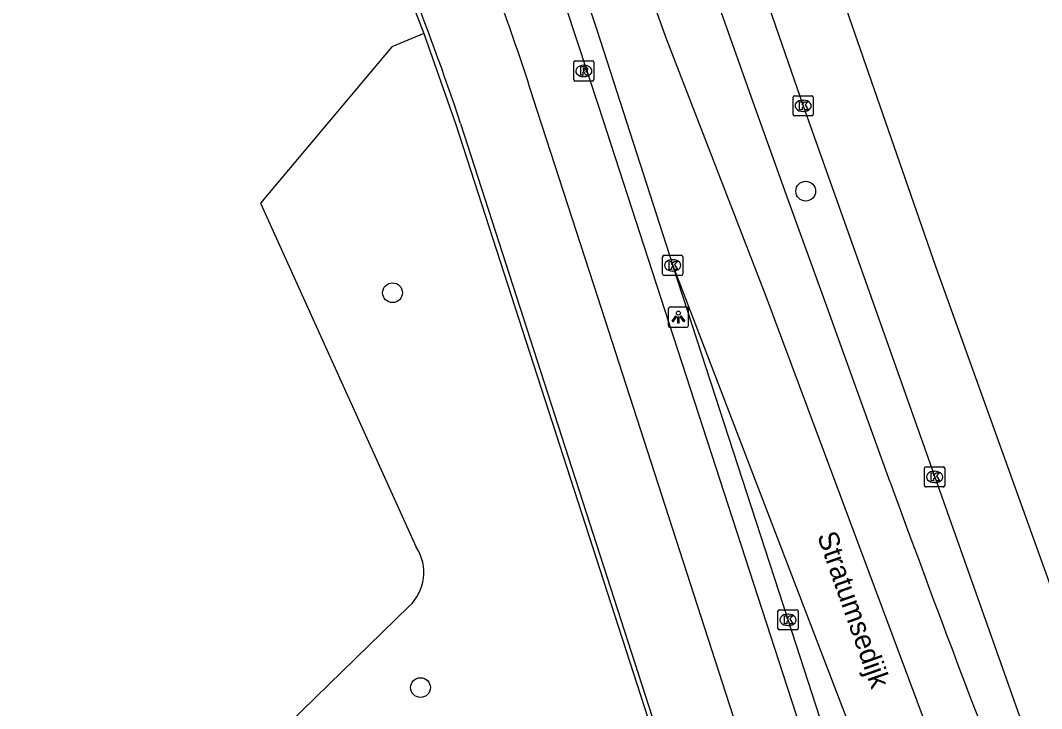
# Model space of a CAD drawing. Extents: x 161402 to 161933, y 381650 to 382313.
# Drawn here: x 161853.9 to 161904.4, y 382229.6 to 382263.7 of the extents above; entities that cross this region are included whole.
import ezdxf

# ---------------------------------------------------------------- set-up
doc = ezdxf.new("R2010")
doc.units = 0
for name, color, linetype in [('IMGEO_Boom', 7, 'Continuous'), ('IMGEO_Fietspad_gesloten', 7, 'Continuous'), ('IMGEO_Groenvoorziening', 7, 'Continuous'), ('IMGEO_Kolk', 7, 'Continuous'), ('IMGEO_Lichtpunt', 7, 'Continuous'), ('IMGEO_Muur', 7, 'Continuous'), ('IMGEO_Openbare_ruimte_label', 7, 'Continuous'), ('IMGEO_OVBaan_gesloten', 7, 'Continuous'), ('IMGEO_Rijbaan_lokaal_gesloten', 7, 'Continuous'), ('IMGEO_Rioolput', 7, 'Continuous')]:
    doc.layers.add(name, color=color, linetype=linetype)

msp = doc.modelspace()

# ---------------------------------------------------------------- linework, layer by layer
at = {"layer": 'IMGEO_Boom'}
for centre in [(161892.739, 382255.252), (161872.299, 382250.226), (161873.682, 382230.683)]:
    msp.add_circle(centre, 0.489, dxfattribs=at)
at = {"layer": 'IMGEO_Fietspad_gesloten'}
for points in [[(161880.873, 382264.356), (161882.494, 382259.457), (161885.56, 382250), (161893.082, 382226.796)], [(161892.685, 382218.361), (161882.447, 382250), (161879.271, 382259.813)]]:
    msp.add_lwpolyline(points, dxfattribs=at)
msp.add_arc((161793.457, 382233.122), 89.869, 17.27756, 23.68225, dxfattribs=at)
at = {"layer": 'IMGEO_Groenvoorziening'}
for points in [[(161873.85, 382263.053), (161872.272, 382262.391), (161865.763, 382254.663), (161873.474, 382237.626)], [(161873.117, 382234.703), (161853.893, 382215.95), (161864.212, 382205.052)]]:
    msp.add_lwpolyline(points, dxfattribs=at)
msp.add_arc((161871.565, 382236.376), 2.282, 312.8579, 33.2155, dxfattribs=at)
at = {"layer": 'IMGEO_Kolk'}
for p, q in [((161892.11, 382259.052), (161892.11, 382259.904)), ((161892.185, 382259.978), (161893.037, 382259.978)), ((161893.111, 382259.904), (161893.111, 382259.052)), ((161892.598, 382259.758), (161892.623, 382259.758)), ((161893.037, 382258.978), (161892.185, 382258.978)), ((161892.621, 382259.198), (161892.596, 382259.198)), ((161885.656, 382251.153), (161885.656, 382252.005)), ((161885.731, 382252.079), (161886.583, 382252.079)), ((161886.144, 382251.859), (161886.169, 382251.859)), ((161886.657, 382252.005), (161886.657, 382251.153)), ((161886.167, 382251.299), (161886.142, 382251.299)), ((161886.583, 382251.079), (161885.731, 382251.079)), ((161898.689, 382241.61), (161899.541, 382241.61)), ((161898.614, 382240.684), (161898.614, 382241.536)), ((161899.102, 382241.39), (161899.127, 382241.39)), ((161899.615, 382241.536), (161899.615, 382240.684)), ((161899.541, 382240.61), (161898.689, 382240.61)), ((161899.125, 382240.83), (161899.1, 382240.83)), ((161891.436, 382234.533), (161892.288, 382234.533)), ((161891.361, 382233.607), (161891.361, 382234.459)), ((161891.849, 382234.313), (161891.874, 382234.313)), ((161892.362, 382234.459), (161892.362, 382233.607)), ((161892.288, 382233.533), (161891.436, 382233.533)), ((161891.872, 382233.753), (161891.847, 382233.753))]:
    msp.add_line(p, q, dxfattribs=at)
for points in [[(161892.11, 382259.052), (161892.11, 382259.904)], [(161892.185, 382259.978), (161893.037, 382259.978)], [(161893.111, 382259.904), (161893.111, 382259.052)], [(161892.431, 382259.678), (161892.554, 382259.678), (161892.554, 382259.527), (161892.684, 382259.678), (161892.848, 382259.678), (161892.702, 382259.527), (161892.855, 382259.278), (161892.703, 382259.278), (161892.618, 382259.442), (161892.554, 382259.375), (161892.554, 382259.278), (161892.431, 382259.278), (161892.431, 382259.678)], [(161893.037, 382258.978), (161892.185, 382258.978)], [(161885.656, 382251.153), (161885.656, 382252.005)], [(161885.731, 382252.079), (161886.583, 382252.079)], [(161885.977, 382251.779), (161886.1, 382251.779), (161886.1, 382251.628), (161886.23, 382251.779), (161886.394, 382251.779), (161886.248, 382251.628), (161886.401, 382251.379), (161886.249, 382251.379), (161886.164, 382251.543), (161886.1, 382251.476), (161886.1, 382251.379), (161885.977, 382251.379), (161885.977, 382251.779)], [(161886.657, 382252.005), (161886.657, 382251.153)], [(161886.583, 382251.079), (161885.731, 382251.079)], [(161898.689, 382241.61), (161899.541, 382241.61)], [(161898.614, 382240.684), (161898.614, 382241.536)], [(161898.935, 382241.31), (161899.058, 382241.31), (161899.058, 382241.159), (161899.188, 382241.31), (161899.352, 382241.31), (161899.206, 382241.159), (161899.359, 382240.91), (161899.207, 382240.91), (161899.122, 382241.074), (161899.058, 382241.007), (161899.058, 382240.91), (161898.935, 382240.91), (161898.935, 382241.31)], [(161899.615, 382241.536), (161899.615, 382240.684)], [(161899.541, 382240.61), (161898.689, 382240.61)], [(161891.436, 382234.533), (161892.288, 382234.533)], [(161891.361, 382233.607), (161891.361, 382234.459)], [(161891.682, 382234.233), (161891.805, 382234.233), (161891.805, 382234.082), (161891.935, 382234.233), (161892.099, 382234.233), (161891.953, 382234.082), (161892.106, 382233.833), (161891.954, 382233.833), (161891.869, 382233.997), (161891.805, 382233.93), (161891.805, 382233.833), (161891.682, 382233.833), (161891.682, 382234.233)], [(161892.362, 382234.459), (161892.362, 382233.607)], [(161892.288, 382233.533), (161891.436, 382233.533)]]:
    msp.add_lwpolyline(points, dxfattribs=at)
for centre, start, end in [((161892.187, 382259.902), 91.552, 178.448), ((161892.187, 382259.902), 91.552, 178.448), ((161893.035, 382259.902), 1.552, 88.448), ((161893.035, 382259.902), 1.552, 88.448), ((161892.187, 382259.054), 181.552, 268.448), ((161892.187, 382259.054), 181.552, 268.448), ((161893.035, 382259.054), 271.552, 358.448), ((161893.035, 382259.054), 271.552, 358.448), ((161885.733, 382252.003), 91.552, 178.448), ((161885.733, 382252.003), 91.552, 178.448), ((161886.581, 382252.003), 1.552, 88.448), ((161886.581, 382252.003), 1.552, 88.448), ((161885.733, 382251.155), 181.552, 268.448), ((161885.733, 382251.155), 181.552, 268.448), ((161886.581, 382251.155), 271.552, 358.448), ((161886.581, 382251.155), 271.552, 358.448), ((161898.691, 382241.534), 91.552, 178.448), ((161898.691, 382241.534), 91.552, 178.448), ((161899.539, 382241.534), 1.552, 88.448), ((161899.539, 382241.534), 1.552, 88.448), ((161898.691, 382240.686), 181.552, 268.448), ((161898.691, 382240.686), 181.552, 268.448), ((161899.539, 382240.686), 271.552, 358.448), ((161899.539, 382240.686), 271.552, 358.448), ((161891.438, 382234.457), 91.552, 178.448), ((161891.438, 382234.457), 91.552, 178.448), ((161892.286, 382234.457), 1.552, 88.448), ((161892.286, 382234.457), 1.552, 88.448), ((161891.438, 382233.609), 181.552, 268.448), ((161891.438, 382233.609), 181.552, 268.448), ((161892.286, 382233.609), 271.552, 358.448), ((161892.286, 382233.609), 271.552, 358.448)]:
    msp.add_arc(centre, 0.0765, start, end, dxfattribs=at)
for centre, major_axis, ratio, start_param, end_param in [((161892.597, 382259.478), (-0.387, 0.002), 0.722429, 4.712389, 7.853982), ((161892.622, 382259.478), (-0.39, 0.002), 0.717154, 1.570796, 4.712389), ((161886.143, 382251.579), (-0.387, 0.002), 0.722429, 4.712389, 7.853982), ((161886.168, 382251.579), (-0.39, 0.002), 0.717154, 1.570796, 4.712389), ((161899.101, 382241.11), (-0.387, 0.002), 0.722429, 4.712389, 7.853982), ((161899.126, 382241.11), (-0.39, 0.002), 0.717154, 1.570796, 4.712389), ((161891.848, 382234.033), (-0.387, 0.002), 0.722429, 4.712389, 7.853982), ((161891.873, 382234.033), (-0.39, 0.002), 0.717154, 1.570796, 4.712389)]:
    msp.add_ellipse(centre, major_axis=major_axis, ratio=ratio, start_param=start_param, end_param=end_param, dxfattribs=at)
at = {"layer": 'IMGEO_Lichtpunt'}
for p, q in [((161885.94, 382249.417), (161885.94, 382248.61)), ((161885.94, 382249.417), (161885.94, 382248.61)), ((161886.842, 382249.512), (161886.034, 382249.512)), ((161886.842, 382249.512), (161886.034, 382249.512)), ((161886.936, 382248.61), (161886.936, 382249.417)), ((161886.936, 382248.61), (161886.936, 382249.417)), ((161886.034, 382248.516), (161886.842, 382248.516)), ((161886.034, 382248.516), (161886.842, 382248.516))]:
    msp.add_line(p, q, dxfattribs=at)
for points in [[(161886.314, 382249.081), (161886.353, 382249.053), (161886.165, 382248.791), (161886.127, 382248.818), (161886.314, 382249.081)], [(161886.416, 382249.033), (161886.463, 382249.033), (161886.463, 382248.711), (161886.416, 382248.711), (161886.416, 382249.033)], [(161886.526, 382249.053), (161886.564, 382249.08), (161886.751, 382248.818), (161886.712, 382248.79), (161886.526, 382249.053)]]:
    msp.add_lwpolyline(points, dxfattribs=at)
msp.add_circle((161886.439, 382249.215), 0.0994, dxfattribs=at)
for centre, start, end in [((161886.034, 382249.417), 90, 180), ((161886.034, 382249.417), 90, 180), ((161886.842, 382249.417), 0, 90), ((161886.842, 382249.417), 0, 90), ((161886.034, 382248.61), 180, 270), ((161886.034, 382248.61), 180, 270), ((161886.842, 382248.61), 270, 0), ((161886.842, 382248.61), 270, 360)]:
    msp.add_arc(centre, 0.0946, start, end, dxfattribs=at)
at = {"layer": 'IMGEO_Muur'}
for points in [[(161872.768, 382265.848), (161873.85, 382263.053)], [(161873.85, 382263.053), (161875.437, 382258.549), (161885.303, 382228.015)], [(161875.668, 382258.603), (161888.595, 382218.562)]]:
    msp.add_lwpolyline(points, dxfattribs=at)
msp.add_arc((161758.183, 382219.653), 123.774, 18.34203, 21.95995, dxfattribs=at)
at = {"layer": 'IMGEO_OVBaan_gesloten'}
for points in [[(161883.94, 382296.053), (161887.492, 382285.515), (161891.555, 382273.464), (161899.181, 382251.493), (161905.587, 382233.642), (161913.746, 382209.878), (161922.363, 382185.389), (161928.921, 382166.622), (161929.639, 382164.026), (161931.896, 382155.865), (161931.923, 382155.731), (161932.527, 382152.775), (161932.932, 382150.79)], [(161888.071, 382272.654), (161889.299, 382269.086), (161892.612, 382259.478), (161895.968, 382250), (161905.286, 382223.681), (161911.442, 382206.261), (161912.81, 382202.422)]]:
    msp.add_lwpolyline(points, dxfattribs=at)
at = {"layer": 'IMGEO_Rijbaan_lokaal_gesloten'}
for points in [[(161926.032, 382143.324), (161923.698, 382154.142), (161918.698, 382173.962), (161914.783, 382185.665), (161890.773, 382250.034), (161885.821, 382262.869), (161874.965, 382293.393)], [(161896.92, 382240.847), (161895.266, 382245.423), (161893.614, 382250), (161891.876, 382254.828), (161890.14, 382259.657), (161886.805, 382269.086), (161885.832, 382271.885)], [(161881.911, 382264.732), (161882.156, 382263.987), (161882.398, 382263.242), (161886.158, 382251.579)], [(161886.158, 382251.579), (161909.37, 382191.051)], [(161904.023, 382199.219), (161895.714, 382222.171), (161895.637, 382222.394), (161891.864, 382234.033), (161886.671, 382250), (161886.158, 382251.579)]]:
    msp.add_lwpolyline(points, dxfattribs=at)
msp.add_arc((162570.89, 382485.384), 716.961, 199.942296, 201.542811, dxfattribs=at)
at = {"layer": 'IMGEO_Rioolput'}
for p, q in [((161881.261, 382260.778), (161881.261, 382261.63)), ((161881.336, 382261.704), (161882.188, 382261.704)), ((161881.749, 382261.484), (161881.774, 382261.484)), ((161882.262, 382261.63), (161882.262, 382260.778)), ((161881.772, 382260.924), (161881.747, 382260.924)), ((161882.188, 382260.704), (161881.336, 382260.704))]:
    msp.add_line(p, q, dxfattribs=at)
for points in [[(161881.261, 382260.778), (161881.261, 382261.63)], [(161881.336, 382261.704), (161882.188, 382261.704)], [(161881.85, 382261.402), (161881.598, 382261.404), (161881.598, 382261.004)], [(161881.776, 382261.323), (161881.722, 382261.323), (161881.722, 382261.242)], [(161882.262, 382261.63), (161882.262, 382260.778)], [(161881.598, 382261.004), (161881.722, 382261.004), (161881.722, 382261.166), (161881.733, 382261.166)], [(161881.722, 382261.242), (161881.774, 382261.242)], [(161881.78, 382261.137), (161881.851, 382261.004), (161881.991, 382261.004), (161881.926, 382261.13)], [(161882.188, 382260.704), (161881.336, 382260.704)]]:
    msp.add_lwpolyline(points, dxfattribs=at)
for centre, radius, start, end in [((161881.338, 382261.628), 0.0765, 91.552, 178.448), ((161881.338, 382261.628), 0.0765, 91.552, 178.448), ((161881.782, 382261.227), 0.0964, 77.0061, 93.1865), ((161881.796, 382261.284), 0.0378, 276.6634, 79.6772), ((161881.849, 382261.292), 0.109, 350.3612, 89.416), ((161882.186, 382261.628), 0.0765, 1.552, 88.448), ((161882.186, 382261.628), 0.0765, 1.552, 88.448), ((161881.338, 382260.78), 0.0765, 181.552, 268.448), ((161881.338, 382260.78), 0.0765, 181.552, 268.448), ((161881.732, 382261.113), 0.0533, 26.0293, 88.6989), ((161881.758, 382261.431), 0.19, 274.7715, 282.9687), ((161881.847, 382261.292), 0.112, 277.5842, 350.9817), ((161881.831, 382261.077), 0.108, 29.5134, 73.7905), ((161882.186, 382260.78), 0.0765, 271.552, 358.448), ((161882.186, 382260.78), 0.0765, 271.552, 358.448)]:
    msp.add_arc(centre, radius, start, end, dxfattribs=at)
for centre, major_axis, ratio, start_param, end_param in [((161881.748, 382261.204), (-0.387, 0.002), 0.722429, 4.712389, 7.853982), ((161881.773, 382261.204), (-0.39, 0.002), 0.717154, 1.570796, 4.712389)]:
    msp.add_ellipse(centre, major_axis=major_axis, ratio=ratio, start_param=start_param, end_param=end_param, dxfattribs=at)

# ---------------------------------------------------------------- texts
at = {"layer": 'IMGEO_Openbare_ruimte_label'}
msp.add_text('Stratumsedijk', height=1, rotation=289.5036, dxfattribs=at).set_placement((161893.293, 382238.201))

doc.saveas('drawing.dxf')
